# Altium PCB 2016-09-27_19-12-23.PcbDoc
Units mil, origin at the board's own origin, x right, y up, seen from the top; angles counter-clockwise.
Board outline 2185 x 2080 mil, 4 copper layers (Top Layer, MidLayer1, MidLayer2, Bottom Layer); 17 components, 9 nets, 36 pads, 60 vias.
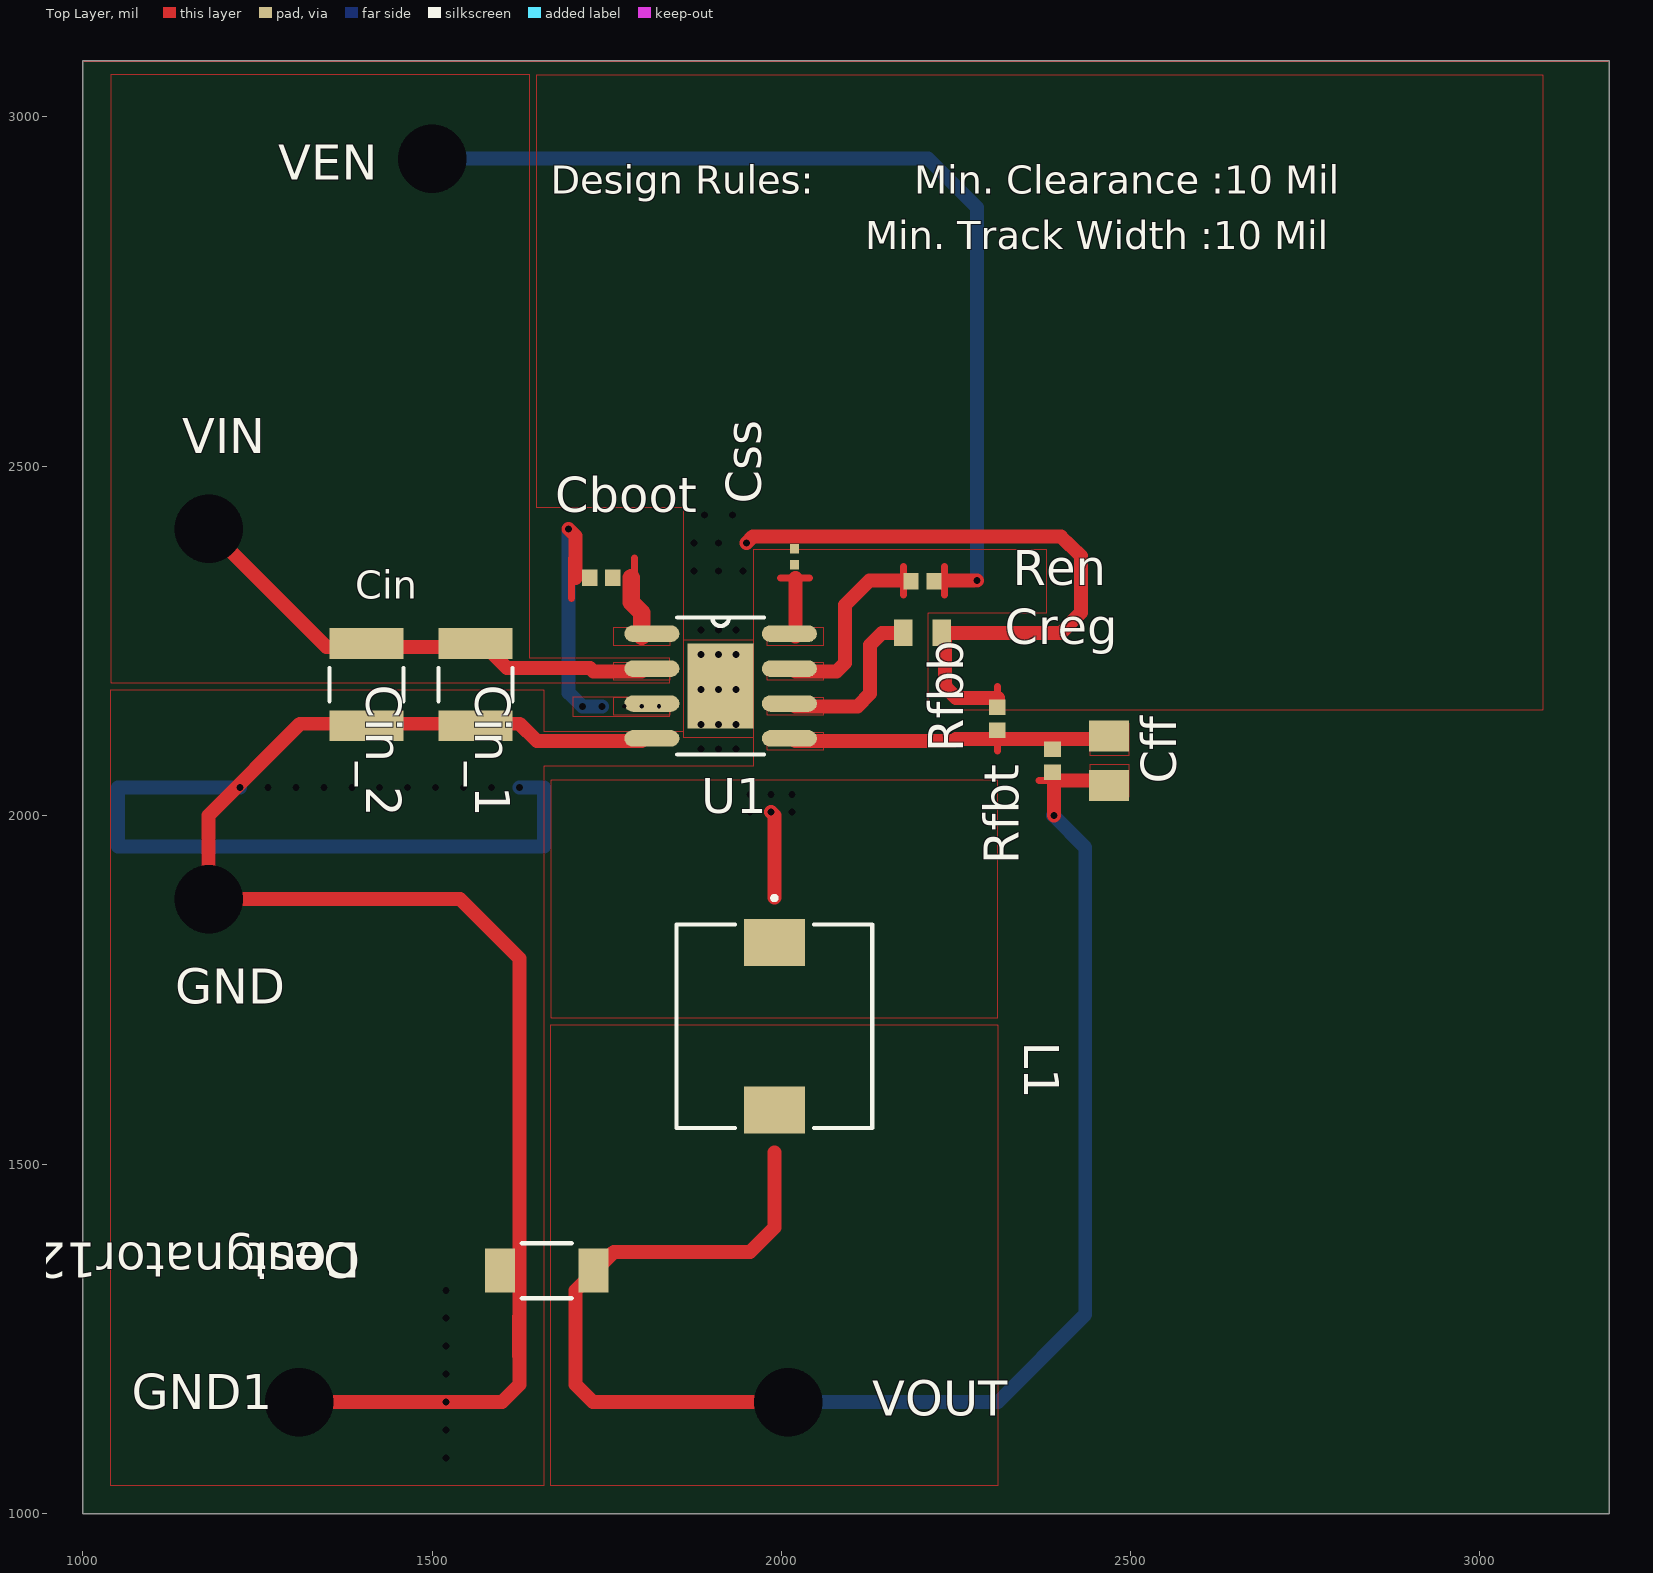
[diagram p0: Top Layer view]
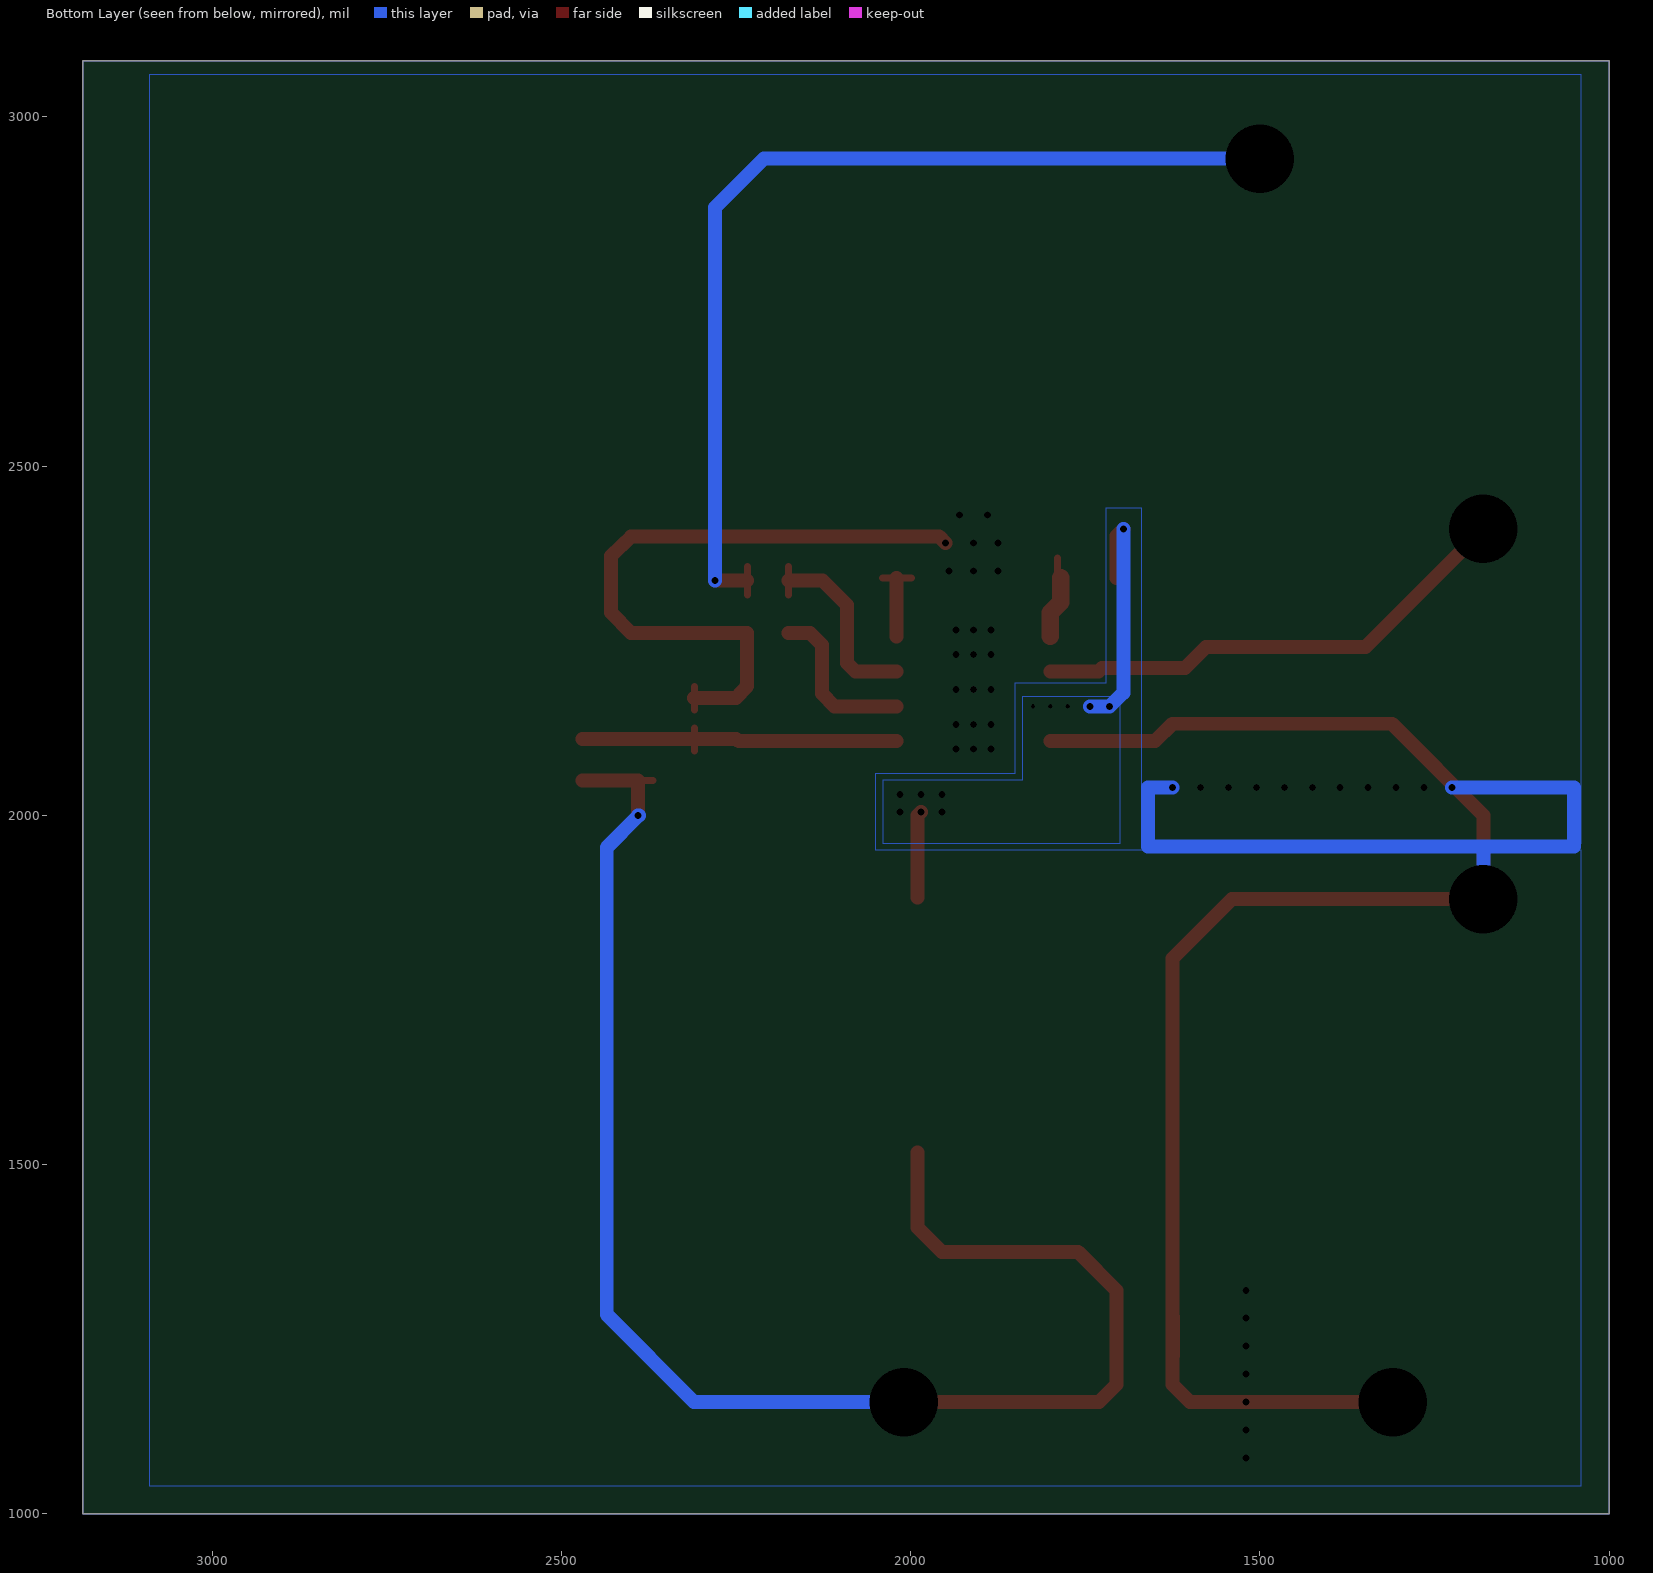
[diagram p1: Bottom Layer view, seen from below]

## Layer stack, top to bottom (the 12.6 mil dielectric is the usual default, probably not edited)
Top Layer: signal copper 1.4
Dielectric: core 12.6, FR-4, Dk 4.8
MidLayer1: signal copper 1.4
Dielectric: prepreg 12.6, FR-4, Dk 4.8
MidLayer2: signal copper 1.4
Dielectric: core 12.6, FR-4, Dk 4.8
Bottom Layer: signal copper 1.4

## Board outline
1000,1000 3185,1000 3185,3080 1000,3080

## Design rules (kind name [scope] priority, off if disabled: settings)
PlaneConnect [All] p0: scope1count=1 scope1_0_kind=Board scope1_0_value=Board scope2count=1 scope2_0_kind=Board scope2_0_value=Board commentlength=0 planeconnectstyle=Direct reliefexpansion=20 reliefentries=4 reliefconductorwidth=10 reliefairgap=10
PlaneConnect [All] p1: planeconnectstyle=Direct reliefexpansion=20 reliefentries=4 reliefconductorwidth=10 reliefairgap=10
PolygonConnect [All] p0: scope1count=1 scope1_0_kind=Board scope1_0_value=Board scope2count=1 scope2_0_kind=Board scope2_0_value=Board commentlength=0 connectstyle=Direct reliefconductorwidth=10 reliefentries=4 polygonreliefangle="90 Angle"
PolygonConnect [All] p1: connectstyle=Direct reliefconductorwidth=10 reliefentries=4 polygonreliefangle="90 Angle"

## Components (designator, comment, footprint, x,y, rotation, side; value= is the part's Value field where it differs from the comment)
Cboot "" 0402 1742,2340 r0 top
Cff "" 0805 2469,2078 r90 top
Cin_1 "" 1210_280 1562,2187 r270 top
Cin_2 "" 1210_280 1406,2187 r270 top
Cout "" 1206 1664,1348 r180 top
Creg "" 0603 2202,2261 r0 top
Css "" 0201 2019,2370 r90 top
GND "" TP-1502 1178,1879 r0 top
GND1 "" TP-1502 1309,1159 r0 top
L1 "" CLF7045 1990,1698 r270 top
Ren "" 0402 2202,2335 r0 top
Rfbb "" 0402 2309,2138 r90 top
Rfbt "" 0402 2388,2078 r90 top
U1 "" DDA0008E 1913,2185 r0 top
VEN "" TP-1502 1498,2938 r0 top
VIN "" TP-1502 1178,2409 r0 top
VOUT "" TP-1502 2009,1159 r0 top

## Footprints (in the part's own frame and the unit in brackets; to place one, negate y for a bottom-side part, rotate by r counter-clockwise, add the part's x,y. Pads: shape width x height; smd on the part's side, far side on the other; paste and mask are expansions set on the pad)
0201 [mil]
  rect 14x13 smd: 1(-11.5,0) 2(11.5,0)
0402 [mil]
  rect 22x24 smd: 1(-16.5,0) 2(16.5,0)
0603 [mil]
  rect 26x38 smd: 1(-27.5,0) 2(27.5,0)
0805 [mil]
  rect 44x57 smd: 1(-35.5,0) 2(35.5,0)
1206 [mm]
  rect 1.1x1.6 smd: 1(-1.7,0) 2(1.7,0)
  silkscreen extent -0.9,-1 0.9,1
1210_280 [mil]
  rect 44x106 smd: 1(-59,0) 2(59,0)
  silkscreen extent -24,-53 24,53
CLF7045 [mil]
  rect 67x87 smd: 1(-120,0) 2(120,0)
  silkscreen extent -186,-140 146,140
DDA0008E [mm]
  oval 2x0.6 smd: 1(-2.5,1.905) 2(-2.5,0.635) 3(-2.5,-0.635) 4(-2.5,-1.905) 5(2.5,-1.905) 6(2.5,-0.635) 7(2.5,0.635) 8(2.5,1.905)
  rect 2.4x3.1 smd: 9(0,0)
  silkscreen extent -1.58,-2.49 1.58,2.49
TP-1502 [mil]
  round 65 / inner round 0 / far side round 65 hole 32: 1(0,0)

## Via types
v1: diameter 0, hole 10, Top Layer to Bottom Layer, 52 vias
v2: diameter 0, hole 98, Top Layer to Bottom Layer, 5 vias
v3: diameter 0, hole 6, Top Layer to Bottom Layer, 3 vias

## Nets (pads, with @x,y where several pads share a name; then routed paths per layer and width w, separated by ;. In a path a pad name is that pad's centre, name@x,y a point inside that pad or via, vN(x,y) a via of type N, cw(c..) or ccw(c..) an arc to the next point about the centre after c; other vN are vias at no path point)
0: Cin_1.2 Cin_2.2 Cout.2 Creg.2 Css.2 GND1.1 GND.1 Rfbb.2 U1.4 U1.9 | length 4359.6
  Top Layer w8: v1(1910,2180) U1.9@1910,2181
  Top Layer w10: 1619.5,1225 1619.5,1283 ; 1999,2398.5 2040,2398.5 ; Rfbb.2@2309.5,2151 2309.5,2184
  Top Layer w20: v2(1310,1160) v1(1520,1160) 1600,1160 1625,1185 1625,1255 1625,1795 1540,1880 v2(1180,1880) 1180,2000 1311,2131 1577,2131 1625,2131 1650,2106 U1.4@1800,2106 ; v1(1950,2390) 1959,2399 2020,2399 2400,2399 2429,2371 2429,2290 2400,2261 2234,2261 2234,2185 2250,2168 2310,2168
  Bottom Layer w20: v2(1180,1880) 1180,1955 ; v1(1225,2040) 1050,2040 1050,1955 1180,1955 ; v1(1625,2040) 1660,2040 1660,1955 1180,1955
  other v1: 1520,1080 1520,1120 1520,1200 1520,1240 1520,1280 1520,1320 1265,2040 1305,2040 1345,2040 1385,2040 1425,2040 1465,2040 1505,2040 1545,2040 1585,2040 1885,2095 1910,2095 1935,2095 1885,2130 1910,2130 1935,2130 1885,2180 1935,2180 1885,2230 1910,2230 1935,2230 1885,2265 1910,2265 1935,2265 1875,2350 1910,2350 1945,2350 1875,2390 1910,2390 1890,2430 1930,2430
1: Cin_1.1 Cin_2.1 Ren.2 U1.2 VIN.1 | length 704.5
  Top Layer w20: v2(1180,2410) 1349,2241 1577,2241 1607,2211 1726,2211 1731,2206 U1.2@1800,2206
2: Cff.1 Cout.1 L1.1 Rfbt.1 VOUT.1 | length 548.1
  Top Layer w10: 1699.5,2310 1699.5,2368
  Top Layer w20: v1(1695,2410) 1705,2400 1705,2340 ; v1(1985,2005) 1990,2000 1990,1882
  Bottom Layer w20: v1(1695,2410) 1695,2175 1696,2175 v1(1715,2156) v1(1743,2156)
  other v1: 1955,2005 2015,2005 1955,2030 1985,2030 2015,2030
  other v3: 1775,2156 1800,2156 1825,2156
3: Creg.1 U1.6 | length 239.5
  Top Layer w20: U1.6@2020,2156 2109,2156 2127,2174 2127,2244 2144,2261 Creg.1@2175,2261
4: Css.1 U1.8 | length 125
  Top Layer w10: 1999,2339.5 2040,2339.5
  Top Layer w20: U1.8@2020,2256 2020,2340
5: Cff.2 Rfbb.1 Rfbt.2 U1.5 | length 525
  Top Layer w10: 2309.5,2092 Rfbb.1@2309.5,2125 ; 2369,2108.5 2410,2108.5
  Top Layer w20: U1.5@2020,2106 2246,2106 2250,2109 2310,2109 2390,2109 Cff.2@2470,2109
6: Cboot.2 L1.2 U1.3 VEN.1 | length 3750.5
  Top Layer w10: 1709.5,1225 1709.5,1283 ; 2233.5,2315 2233.5,2356 ; 2369,2049.5 2410,2049.5
  Top Layer w20: 1990,1517 1990,1410 1955,1375 1760,1375 1705,1320 1705,1255 1705,1185 1730,1160 v2(2010,1160) ; 2234,2336 v1(2280,2336) ; v1(2390,2000) 2390,2050 2470,2050
  Bottom Layer w20: v2(1500,2940) 2210,2940 2280,2870 v1(2280,2336) ; v2(2010,1160) 2310,1160 2435,1285 2435,1954 2390,1999 ; 2389,2000 2390,1999 ; v1(2390,2000) 2390,1999
7: Ren.1 U1.7 | length 298.5
  Top Layer w10: 2174.5,2315 2174.5,2356
  Top Layer w20: U1.7@2020,2206 2079,2206 2091,2218 2091,2301 2126,2336 Ren.1@2175,2336
8: Cboot.1 U1.1 | length 148.2
  Top Layer w10: 1789.5,2310 1789.5,2368
  Top Layer w25: 1785,2340 1785,2305 1800,2290 U1.1@1800,2256

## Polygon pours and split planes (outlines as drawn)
4 on Top Layer " " (solid, pour order 0): 1980,2243 1980,2269 2060,2269 2060,2243
7 on Top Layer " " (solid, pour order 1): 1980,2193 1980,2219 2060,2219 2060,2193
3 on Top Layer " " (solid, pour order 2): 1980,2143 1980,2169 2060,2169 2060,2143
5 on Top Layer " " (solid, pour order 3): 1980,2093 1980,2119 2060,2119 2060,2093
2 on Top Layer " " (solid, pour order 4): 1760,2143 1760,2169 1840,2169 1840,2143
1 on Top Layer " " (solid, pour order 5): 1760,2193 1760,2219 1840,2219 1840,2193
8 on Top Layer " " (solid, pour order 6): 1760,2243 1760,2269 1840,2269 1840,2243
5 on Top Layer " " (solid, pour order 7): 2442,2085 2442,2132 2497,2132 2497,2085
6 on Top Layer " " (solid, pour order 8): 2442,2026 2442,2073 2497,2073 2497,2026
2 on Top Layer " " (solid, pour order 9): 2310,1710 2310,2050 1670,2050 1670,1710
6 on Top Layer " " (solid, pour order 10): 1670,1700 2310,1700 2310,1040 1670,1040
2 on Top Layer " " (solid, pour order 11): 1840,2169 1701,2169 1701,2142 1840,2142
1 on Top Layer " " (solid, pour order 12): 1040,2190 1840,2190 1840,2225 1640,2225 1640,3060 1040,3060
0 on Top Layer " " (solid, pour order 14): 1860,2111 1860,2251 1960,2251 1960,2111
0 on Top Layer " " (solid, pour order 15): 1860,2120 1860,2440 1650,2440 1650,3060 3090,3060 3090,2150 2210,2150 2210,2290 2380,2290 2380,2380 1960,2380 1960,2070 1660,2070 1660,1040 1040,1040 1040,2180 1660,2180 1660,2120
2 on Bottom Layer " " (solid, pour order 13): 1840,2170 1840,2050 2040,2050 2040,1960 1700,1960 1700,2170
0 on Bottom Layer " " (solid, pour order 16): 1040,3060 3090,3060 3090,1040 1040,1040 1040,1950 2050,1950 2050,2060 1850,2060 1850,2190 1720,2190 1720,2440 1670,2440 1670,1960 1040,1960
0 on MidLayer2 " " (solid, pour order 17): 1040,3060 3090,3060 3090,1040 1040,1040 1040,1220 1040,3055
0 on MidLayer1 " " (solid, pour order 18): 1040,3060 1040,1040 3090,1040 3090,3060

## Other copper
Multi-Layer:
  the board outline again, w1

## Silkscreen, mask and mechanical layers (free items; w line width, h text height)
Top Overlay:
  text "Design Rules:" at 1670,2890 h40
  text "Min. Clearance :10 Mil" at 2190,2890 h40
  text "Min. Track Width :10 Mil" at 2120,2810 h40
  text "Cin" at 1390,2310 h40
